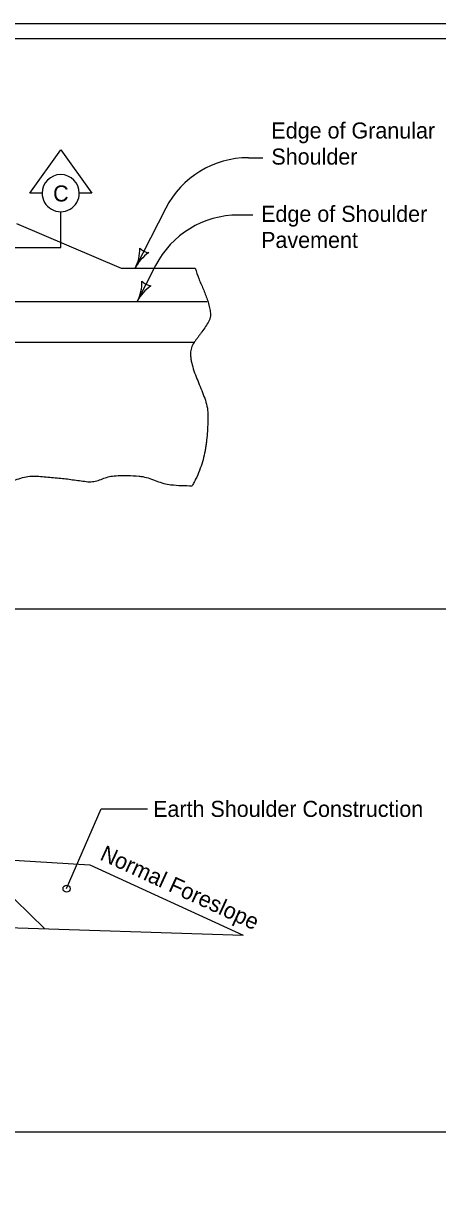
# Model space of a CAD drawing. Extents: x 9538 to 81668, y 7600 to 11751.
# Drawn here: x 19008 to 19420, y 8774 to 9944 of the extents above; entities that cross this region are included whole.
import ezdxf

# ---------------------------------------------------------------- set-up
doc = ezdxf.new("R2010")
doc.units = 0
for name, color, linetype in [('Default', 7, 'Continuous'), ('DsnShtMinorGrid14', 7, 'Continuous'), ('dsnStdNameDate', 7, 'Continuous'), ('dsnStdNote', 7, 'Continuous'), ('dsnStdPattern', 7, 'Continuous'), ('dsnStdShading', 7, 'Continuous'), ('dsnStdTable', 7, 'Continuous')]:
    doc.layers.add(name, color=color, linetype=linetype)

msp = doc.modelspace()

# ---------------------------------------------------------------- linework, layer by layer
at = {"layer": 'Default'}
msp.add_lwpolyline([(17332.5, 9944), (20467.5, 9944), (20467.5, 7924), (17332.5, 7924)], close=True, dxfattribs=at)
at = {"layer": 'DsnShtMinorGrid14'}
msp.add_circle((19050.7, 9082.6), 3.54, dxfattribs=at)
at = {"layer": 'dsnStdNameDate'}
for p, q in [((19503.1, 9361), (17347.5, 9361)), ((19503.1, 8840), (17347.5, 8840))]:
    msp.add_line(p, q, dxfattribs=at)
at = {"layer": 'dsnStdNote'}
for p, q in [((19231.7, 9810.4), (19246.1, 9810.4)), ((19149.4, 9760.1), (19118.9, 9700.3)), ((19221.6, 9753.4), (19235.9, 9753.4)), ((19139.3, 9703), (19121, 9667.3)), ((19050.7, 9082.6), (19085, 9162)), ((19085, 9162), (19131.4, 9162))]:
    msp.add_line(p, q, dxfattribs=at)
for centre, radius, start, end in [((19231.7, 9718), 92.4, 90, 152.9341), ((19221.6, 9660.9), 92.4, 90, 152.9341), ((19081.1, 9719.6), 42.5, 332.9341, 1.0066), ((19156.7, 9681), 42.5, 124.8616, 152.9341), ((19135.1, 9732), 16.4, 225.2008, 260.6675), ((19083.2, 9686.6), 42.5, 332.9341, 1.0066), ((19137.2, 9699), 16.4, 225.2008, 260.6675), ((19158.9, 9648), 42.5, 124.8616, 152.9341)]:
    msp.add_arc(centre, radius, start, end, dxfattribs=at)
at = {"layer": 'dsnStdPattern'}
for p, q in [((19044.9, 9721.1), (19044.9, 9756.6)), ((18956.8, 9721.1), (19044.9, 9721.1))]:
    msp.add_line(p, q, dxfattribs=at)
msp.add_lwpolyline([(19026.4, 9775.1), (19014.1, 9775.1), (19044.9, 9818.2), (19075.7, 9775.1), (19063.4, 9775.1)], dxfattribs=at)
for start, end in [(0.0008, 179.9992), (179.9992, 0.0008)]:
    msp.add_arc((19044.9, 9775.1), 18.5, start, end, dxfattribs=at)
at = {"layer": 'dsnStdShading'}
msp.add_line((17347.5, 9929), (20443.2, 9929), dxfattribs=at)
at = {"layer": 'dsnStdTable'}
for p, q in [((19000.8, 9744.9), (19104.9, 9700.3)), ((19104.9, 9700.3), (19178.7, 9700.3)), ((19137.3, 9699.1), (19121, 9667.3)), ((17543, 9667.3), (19190.5, 9667.3)), ((17564.2, 9626.7), (19178, 9626.7)), ((18939.2, 9114.6), (19074, 9106.2)), ((19074, 9106.2), (19226.6, 9036.2)), ((18999.2, 9071.7), (19029, 9042.7)), ((18743.2, 9052), (19226.6, 9036.2))]:
    msp.add_line(p, q, dxfattribs=at)
for points in [[(19178.7, 9700.3), (19182.2, 9690.2), (19186.6, 9679.8), (19190.7, 9669.1), (19192.4, 9663.7), (19193.5, 9658.3), (19193.9, 9652.9), (19193.7, 9651.5), (19193.4, 9650.2), (19192.3, 9647.6), (19185.4, 9637.1), (19183.4, 9634.4), (19181.5, 9631.8), (19179.5, 9629.2), (19177.6, 9626.5), (19175, 9621.1), (19174, 9615.7), (19174.2, 9611.8), (19174.8, 9607.9), (19176.8, 9600.2), (19182.8, 9584.5), (19188.8, 9568.8), (19190.8, 9560.9), (19191.4, 9553.1), (19191.2, 9544.5), (19190.7, 9535.9), (19189.8, 9527.1), (19189.2, 9522.8), (19188.5, 9518.5), (19186.5, 9509.7), (19183.8, 9501.1), (19180.2, 9492.4), (19178, 9488.1), (19176.9, 9486), (19175.6, 9483.8)], [(18895.9, 9487.6), (18897.9, 9487.7), (18905.5, 9488.2), (18913, 9488.8), (18920.6, 9489.6), (18928.1, 9490.5), (18932.9, 9491.5), (18937.6, 9493), (18942.2, 9494.3), (18944.6, 9494.8), (18946.9, 9495.1), (18953.5, 9495.1), (18960.1, 9494.4), (18966.7, 9493.4), (18973.2, 9492.2), (18977.2, 9491.3), (18981.2, 9490.1), (18985.1, 9489), (18989.1, 9488.3), (18992.7, 9488.2), (18996.2, 9488.7), (19003.3, 9490.7), (19010.5, 9492.7), (19017.6, 9493.4), (19032.2, 9492.4), (19046.7, 9491.1), (19053.4, 9490.3), (19060.1, 9489.3), (19066.8, 9488.4), (19073.5, 9487.7), (19079.3, 9488.3), (19085, 9490.1), (19090.6, 9492.1), (19096.3, 9493.4), (19103.8, 9493.9), (19111.4, 9494), (19122.8, 9493.3), (19126.6, 9492.8), (19133.6, 9491), (19140.5, 9488.4), (19147.4, 9486.1), (19154.5, 9484.8), (19175.6, 9483.8)]]:
    msp.add_spline(points, degree=3, dxfattribs=at)

# ---------------------------------------------------------------- texts
at = {"layer": 'dsnStdNote'}
for s, p in [('Edge of Granular', (19254.5, 9829.5)), ('Shoulder', (19254.5, 9803.5)), ('Edge of Shoulder', (19244.3, 9746.5)), ('Pavement', (19244.3, 9720.5)), ('Earth Shoulder Construction', (19136.8, 9154))]:
    msp.add_text(s, height=16, dxfattribs=at).set_placement(p)
msp.add_text('Normal Foreslope', height=16, rotation=335.372, dxfattribs=at).set_placement((19082.9, 9111.8))
at = {"layer": 'dsnStdPattern'}
msp.add_text('C', height=16, dxfattribs=at).set_placement((19037.3, 9766.8))

doc.saveas('drawing.dxf')
